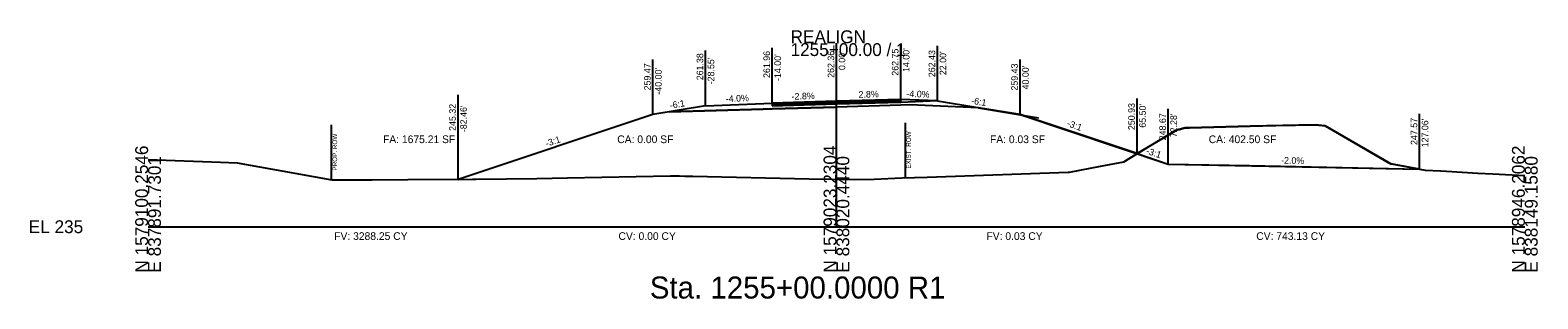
# Model space of a CAD drawing. Extents: x -26 to 6303, y -16 to 9563.
# Drawn here: x 2974.3 to 3302.8, y 6984.3 to 7042.8 of the extents above; entities that cross this region are included whole.
import ezdxf

# ---------------------------------------------------------------- set-up
doc = ezdxf.new("R2010")
doc.units = 0
for name, color, linetype in [('ASPHALT_19MM1', 7, 'Continuous'), ('ASPHALT_9_5MM1', 7, 'Continuous'), ('CONST_LV3', 7, 'Continuous'), ('CONST_PROF_LV1', 7, 'Continuous'), ('Draft_XS_Grid', 7, 'Continuous'), ('Draft_XS_Text', 7, 'Continuous'), ('DTM_TEMP_DROP', 7, 'Continuous'), ('DTM_X_FLOW_ARROWS', 7, 'Continuous'), ('DTM_X_GROUND', 7, 'Continuous'), ('TRANS_BRIDGE', 7, 'Continuous'), ('XS_CELL', 7, 'Continuous'), ('XS_M_SHAPES_EARTHWORK', 7, 'Continuous'), ('XS_P_GROUND', 7, 'Continuous'), ('XS_P_NULL_POINT', 7, 'Continuous'), ('XS_P_ROW', 7, 'Continuous'), ('XS_P_SHOULDER', 7, 'Continuous'), ('XS_P_SUBGRADE_GRANULAR', 7, 'Continuous'), ('XS_P_TX_CLEARZONE', 7, 'Continuous'), ('XS_P_TX_FS_BS', 7, 'Continuous'), ('XS_PLAN_CLEAR_ZONE', 7, 'Continuous'), ('XS_SHEET_EW_TX_AREA', 7, 'Continuous'), ('XS_SHEET_EW_TX_VOLUME', 7, 'Continuous'), ('XS_X_ROW', 7, 'Continuous')]:
    doc.layers.add(name, color=color, linetype=linetype)

msp = doc.modelspace()

# ---------------------------------------------------------------- linework, layer by layer
at = {"layer": 'ASPHALT_19MM1'}
msp.add_lwpolyline([(3136, 7026.36), (3136, 7026.36), (3136, 7026.36), (3150, 7026.75), (3150, 7026.75), (3164, 7027.14), (3164, 7027.14), (3164, 7027.41), (3150, 7027.02), (3150, 7027.02), (3136, 7026.63), (3136, 7026.63), (3136, 7026.36)], dxfattribs=at)
at = {"layer": 'ASPHALT_9_5MM1'}
msp.add_lwpolyline([(3136, 7026.84), (3136, 7026.84), (3136, 7026.84), (3150, 7027.23), (3150, 7027.23), (3164, 7027.62), (3164, 7027.62), (3164, 7027.75), (3150, 7027.36), (3150, 7027.36), (3136, 7026.96), (3136, 7026.96), (3136, 7026.84)], dxfattribs=at)
at = {"layer": 'CONST_LV3'}
for points in [[(3150, 7027.36), (3164, 7027.08)], [(3172, 7027.43), (3164, 7027.08), (3164, 7027.08)], [(3113.54, 7025.06), (3110, 7024.47)], [(3180.96, 7025.93), (3194, 7023.76)]]:
    msp.add_lwpolyline(points, dxfattribs=at)
at = {"layer": 'DTM_X_GROUND'}
msp.add_lwpolyline([(3000, 7014.64), (3015.76, 7014.06), (3019.41, 7013.95), (3032.01, 7011.66), (3040.05, 7010.22), (3045.58, 7010.24), (3048.84, 7010.25), (3056.62, 7010.28), (3070.71, 7010.33), (3071.46, 7010.34), (3078.09, 7010.44), (3084.75, 7010.54), (3091.42, 7010.64), (3113.85, 7011.06), (3114.48, 7011.07), (3115.12, 7011.07), (3115.83, 7011.06), (3116.94, 7011.04), (3118.73, 7011.01), (3144.06, 7010.47), (3153.88, 7010.32), (3158.21, 7010.4), (3164.25, 7010.62), (3169.76, 7010.82), (3200.49, 7011.91), (3200.76, 7011.92), (3207.55, 7013.21), (3212.59, 7014.16), (3223.62, 7020.85), (3223.96, 7021.06), (3224.65, 7021.22), (3226.01, 7021.53), (3226.96, 7021.56), (3240.14, 7021.93), (3245.77, 7022.05), (3254.3, 7022.23), (3255.85, 7022.04), (3256.47, 7021.96), (3270.26, 7014.03), (3270.77, 7013.73), (3270.91, 7013.71), (3270.97, 7013.7), (3278.32, 7012.34), (3281.73, 7012.16), (3282.9, 7012.1), (3289.74, 7011.69), (3293.06, 7011.5), (3300, 7011.14)], dxfattribs=at)
at = {"layer": 'XS_CELL'}
for p, q in [((3150, 7000), (3150, 7040)), ((3000, 7000), (3150, 7000)), ((3150, 7000), (3300, 7000))]:
    msp.add_line(p, q, dxfattribs=at)
at = {"layer": 'XS_M_SHAPES_EARTHWORK'}
msp.add_lwpolyline([(3067.54, 7010.32), (3070.71, 7010.33), (3071.46, 7010.34), (3078.09, 7010.44), (3084.75, 7010.54), (3091.42, 7010.64), (3113.85, 7011.06), (3114.48, 7011.07), (3115.12, 7011.07), (3115.83, 7011.06), (3116.94, 7011.04), (3118.73, 7011.01), (3144.06, 7010.47), (3153.88, 7010.32), (3158.21, 7010.4), (3164.25, 7010.62), (3169.76, 7010.82), (3200.49, 7011.91), (3200.76, 7011.92), (3207.55, 7013.21), (3212.59, 7014.16), (3215.5, 7015.93), (3190, 7024.43), (3180.96, 7025.93), (3166, 7026.53), (3164, 7026.48), (3150, 7026.08), (3136, 7025.69), (3134, 7025.64), (3113.54, 7025.06), (3110, 7024.47)], close=True, dxfattribs=at)
at = {"layer": 'XS_P_GROUND'}
for points in [[(3172, 7027.43), (3190, 7024.43), (3215.5, 7015.93)], [(3172, 7027.43), (3190, 7024.43), (3222.28, 7013.67)], [(3121.45, 7026.38), (3110, 7024.47), (3067.54, 7010.32)], [(3222.28, 7013.67), (3240.02, 7013.31)], [(3240.02, 7013.31), (3277.06, 7012.57)]]:
    msp.add_lwpolyline(points, dxfattribs=at)
at = {"layer": 'XS_P_ROW'}
msp.add_line((3040, 7010.23), (3040, 7022.23), dxfattribs=at)
at = {"layer": 'XS_P_SHOULDER'}
for points in [[(3172, 7027.43), (3172, 7027.43), (3164, 7027.75)], [(3121.45, 7026.38), (3136, 7026.96), (3136, 7026.96)]]:
    msp.add_lwpolyline(points, dxfattribs=at)
at = {"layer": 'XS_P_SUBGRADE_GRANULAR'}
for points in [[(3113.54, 7025.06), (3134, 7025.64), (3134, 7025.64), (3134, 7025.64), (3136, 7025.69)], [(3136, 7025.69), (3136, 7025.69), (3150, 7026.08)], [(3164, 7026.48), (3150, 7026.08), (3150, 7026.08)], [(3180.96, 7025.93), (3180.96, 7025.93), (3166, 7026.53), (3164, 7026.48), (3164, 7026.48)]]:
    msp.add_lwpolyline(points, dxfattribs=at)
at = {"layer": 'XS_P_TX_CLEARZONE'}
for p, q in [((3121.45, 7026.38), (3121.45, 7038.38)), ((3136, 7026.96), (3136, 7038.96)), ((3150, 7027.36), (3150, 7039.36)), ((3164, 7027.75), (3164, 7039.75)), ((3172, 7027.43), (3172, 7039.43)), ((3172, 7027.43), (3172, 7039.43)), ((3110, 7024.47), (3110, 7036.47)), ((3190, 7024.43), (3190, 7036.43)), ((3067.54, 7010.32), (3067.54, 7028.74)), ((3215.5, 7015.93), (3215.5, 7027.93)), ((3222.28, 7013.67), (3222.28, 7025.67)), ((3277.06, 7012.57), (3277.06, 7024.57))]:
    msp.add_line(p, q, dxfattribs=at)
at = {"layer": 'XS_P_TX_FS_BS'}
msp.add_lwpolyline([(3215.5, 7015.93), (3222.28, 7013.67), (3277.06, 7012.57), (3270.84, 7013.72), (3256.47, 7021.96), (3254.3, 7022.23), (3240.14, 7021.93), (3226.96, 7021.56), (3226.01, 7021.53), (3224.31, 7021.14)], close=True, dxfattribs=at)
at = {"layer": 'XS_PLAN_CLEAR_ZONE'}
msp.add_lwpolyline([(3136, 7026.63), (3136, 7026.63), (3136, 7026.63), (3150, 7027.02), (3150, 7027.02), (3164, 7027.41), (3164, 7027.41), (3164, 7027.62), (3150, 7027.23), (3150, 7027.23), (3136, 7026.84), (3136, 7026.84), (3136, 7026.63)], dxfattribs=at)
at = {"layer": 'XS_X_ROW'}
msp.add_line((3165.02, 7010.65), (3165.02, 7022.65), dxfattribs=at)

# ---------------------------------------------------------------- texts
at = {"layer": 'CONST_PROF_LV1'}
for p in [(3215.43, 7015.81), (3067.46, 7010.2)]:
    msp.add_text('X', height=0.24, dxfattribs=at).set_placement(p)
at = {"layer": 'Draft_XS_Grid'}
msp.add_text('-', height=0.0001, dxfattribs=at).set_placement((3000, 7000))
at = {"layer": 'Draft_XS_Text'}
msp.add_text('Sta. 1255+00.0000 R1', height=4.8, dxfattribs=at).set_placement((3109.33, 6984.35))
at = {"layer": 'DTM_TEMP_DROP'}
for p in [(3149.92, 7027.24), (3163.92, 7027.63), (3135.92, 7026.84)]:
    msp.add_text('X', height=0.24, dxfattribs=at).set_placement(p)
at = {"layer": 'DTM_X_FLOW_ARROWS'}
msp.add_text('X', height=0.24, dxfattribs=at).set_placement((3276.98, 7012.45))
at = {"layer": 'TRANS_BRIDGE'}
for p in [(3215.43, 7015.81), (3067.46, 7010.2)]:
    msp.add_text('X', height=0.24, dxfattribs=at).set_placement(p)
at = {"layer": 'XS_CELL'}
for s, p in [('REALIGN', (3140, 7040)), ('1255+00.00 / 1', (3140, 7037.2)), ('EL 235', (2974, 6998.6))]:
    msp.add_text(s, height=2.8, dxfattribs=at).set_placement(p)
for s, p in [('N 1579100.2546', (3000, 6990)), ('N 1579023.2304', (3150, 6990)), ('N 1578946.2062', (3300, 6990)), ('E 837891.7301', (3002.8, 6990)), ('E 838020.4440', (3152.8, 6990)), ('E 838149.1580', (3302.8, 6990))]:
    msp.add_text(s, height=2.8, rotation=90, dxfattribs=at).set_placement(p)
at = {"layer": 'XS_P_GROUND'}
for p in [(3109.92, 7024.35), (3193.92, 7023.64)]:
    msp.add_text('X', height=0.24, dxfattribs=at).set_placement(p)
at = {"layer": 'XS_P_NULL_POINT'}
for p in [(3171.92, 7027.31), (3189.92, 7024.31)]:
    msp.add_text('X', height=0.24, dxfattribs=at).set_placement(p)
at = {"layer": 'XS_P_ROW'}
msp.add_text('PROP. ROW', height=1, rotation=90, dxfattribs=at).set_placement((3041.2, 7012.23))
at = {"layer": 'XS_P_SHOULDER'}
for p in [(3171.92, 7027.31), (3121.37, 7026.26)]:
    msp.add_text('X', height=0.24, dxfattribs=at).set_placement(p)
at = {"layer": 'XS_P_SUBGRADE_GRANULAR'}
msp.add_text('X', height=0.24, dxfattribs=at).set_placement((3222.21, 7013.55))
at = {"layer": 'XS_P_TX_CLEARZONE'}
for s, p in [('261.38', (3120.97, 7031.92)), ('261.96', (3135.52, 7032.42)), ("-14.00'", (3137.92, 7031.76)), ('262.36', (3149.52, 7032.45)), ("0.00'", (3151.92, 7034.14)), ('262.75', (3163.52, 7032.92)), ("14.00'", (3165.92, 7033.72)), ('262.43', (3171.52, 7032.6)), ("22.00'", (3173.92, 7033.04)), ('259.47', (3109.52, 7029.72)), ("-40.00'", (3111.92, 7028.79)), ("-28.55'", (3123.37, 7031.04)), ('259.43', (3189.52, 7029.67)), ("40.00'", (3191.92, 7029.92)), ('245.32', (3067.06, 7020.89)), ("-82.46'", (3069.46, 7020.61)), ('250.93', (3215.02, 7021.06)), ("65.50'", (3217.42, 7021.58)), ('248.67', (3221.8, 7018.84)), ("72.28'", (3224.2, 7019.5)), ('247.57', (3276.58, 7017.82)), ("127.06'", (3278.98, 7017.3))]:
    msp.add_text(s, height=1.44, rotation=90, dxfattribs=at).set_placement(p)
at = {"layer": 'XS_P_TX_FS_BS'}
for s, rotation, p in [('-6:1', 9.4642, (3113.8, 7025.71)), ('-4.0%', 2.2906, (3125.91, 7027.16)), ('-2.8%', 1.6039, (3140.25, 7027.68)), ('2.8%', 1.6039, (3154.84, 7028.09)), ('-4.0%', 357.7094, (3165.23, 7028.3)), ('-6:1', 350.5377, (3179.28, 7026.82)), ('-3:1', 339.9839, (3200.09, 7021.98)), ('-3:1', 18.4332, (3086.86, 7017.39)), ('-3:1', 341.5721, (3217.36, 7015.94)), ('-2.0%', 358.8542, (3246.89, 7013.77))]:
    msp.add_text(s, height=1.44, rotation=rotation, dxfattribs=at).set_placement(p)
at = {"layer": 'XS_SHEET_EW_TX_AREA'}
for s, p in [('FA: 1675.21 SF', (3051.2, 7018.22)), ('CA: 0.00 SF', (3102.24, 7018.22)), ('FA: 0.03 SF', (3183.46, 7018.22)), ('CA: 402.50 SF', (3231.12, 7018.22))]:
    msp.add_text(s, height=1.68, dxfattribs=at).set_placement(p)
at = {"layer": 'XS_SHEET_EW_TX_VOLUME'}
for s, p in [('FV: 3288.25 CY', (3040.56, 6997.12)), ('CV: 0.00 CY', (3102.51, 6997.12)), ('FV: 0.03 CY', (3182.69, 6997.12)), ('CV: 743.13 CY', (3241.48, 6997.12))]:
    msp.add_text(s, height=1.68, dxfattribs=at).set_placement(p)
at = {"layer": 'XS_X_ROW'}
msp.add_text('EXIST. ROW', height=1, rotation=90, dxfattribs=at).set_placement((3166.22, 7012.65))

doc.saveas('drawing.dxf')
